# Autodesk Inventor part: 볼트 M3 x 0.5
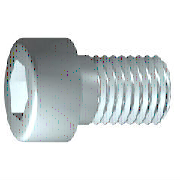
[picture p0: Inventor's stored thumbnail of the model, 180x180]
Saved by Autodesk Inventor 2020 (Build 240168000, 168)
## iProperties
Company: 한국ATC센터
IsCustomPart: 1
Created: 2015-12
Part Number: 볼트 M3 x 0.5
Material: 스테인리스강
Description: 6각머리 태핑 나사
Document SubType Name: Modeling
Standard: KS B 1003
Designer: mdu
Standards Organization: KS
Language: ko-KR
Size Designation: M 4 x 12
Categories: <MemberInstance><Categories><Category DisplayName="조임쇠" InternalName="e4da775c-781d-43d5-af7c-5136215cf5a6" Mnemonic="FSTN"><Category DisplayName="볼트" InternalN
Density: 8.08 g/cm^3
Mass: 1.35567 g
Surface Area: 2.48975 cm^2
Volume: 0.167781 cm^3
Appearance: 반광택
Author: mdu
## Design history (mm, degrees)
sketch "스케치1"
  geometry: L1 (-0.867, 0)-(15, 0); L2 (15, 0)-(15, 1.5); L3 (15, 1.5)-(1.25, 1.5); L4 (1.25, 1.5)-(0.943, 1.5); L5 (0.943, 1.5)-(0, 1.5); L6 (0, 1.5)-(0, 2.75); L7 (0, 2.75)-(-3, 2.75); L8 (-3, 2.75)-(-3, 1.443); L9 (-3, 1.443)-(-1.7, 1.443); L10 (-1.7, 1.443)-(-0.867, 0); L11 (-6.6, 0)-(18.6, 0) reference; L12 (0, -0.55)-(0, 3.3) reference; L13 (1.25, 1.5)-(0, 1.5)
  constraints: 22 end point, 6 parallel, 2 collinear, 2 perpendicular, 1 horizontal, 1 point on line
  dimensions: "d1" = 13.75 distance from line of L3.end L2 (= GEL); "d2" = 0.30683 distance of L4.end L3.end (computed from GAL); "d3" = 3 distance between parallel lines of L8 L6 (= KOH); "d4" = 1.3 distance of L8.end L9.end (= INTI); "d5" = 60 deg angle of L10 L1; "d6" = 3 diameter of L3 L1 (= GD); "d7" = 3 diameter of L5 L1 (= BDM); "d8" = 2.88675 diameter of L9 L1 (= 1.1547 x SW); "d9" = 5.5 diameter of L7 L1 (= KOD); "d26" = 15 distance between parallel lines of L12 L2 (= NLG)
revolve "본체" sketch "스케치1" stored, may be unused: angle "d10" = 90 deg
sketch "스케치2"
  geometry: L1 (0, -3.85)-(0, 3.85) reference; L2 (-3.85, 0)-(3.85, 0) reference; L3 (1.443, 0)-(0.722, -1.25); L4 (0.722, -1.25)-(-0.722, -1.25); L5 (-0.722, -1.25)-(-1.443, 0); L6 (-1.443, 0)-(-0.722, 1.25); L7 (-0.722, 1.25)-(0.722, 1.25); L8 (0.722, 1.25)-(1.443, 0); 2 further points
  constraints: 12 end point, 1 coincident, 1 horizontal alignment, 1 point on line, 12 other
extrude "슬롯" join sketch "스케치2" stored distance "d11" = 10; taper "d12" = 0 deg
workplane "Work Plane1"
fillet "Fillet2" dims "d30" = 0.1 (= R)
body "Solid1"
fillet "모깎기1" dims "d17" = 0.3 (= RR)
feature "스레드" dims "d13" = 13.75 (= GEL), "d14" = 0
chamfer "모따기1" distance "d15" = 0.30673 (= -0.5 x SPD + 0.5 x GD); stored, may be unused: second distance "d16" = 0.30673 (= GUL), angle "d27" = 45 deg
other parameters: "GD" = 3 (= NND) [user parameter; used in 2 equation terms], "NLG" = 15 [user parameter; used in 1 equation term], "GEL" = 13.75 [user parameter; used in 2 equation terms], "KOD" = 5.5 [user parameter; used in 1 equation term], "KOH" = 3 [user parameter; used in 1 equation term], "INTI" = 1.3 [user parameter; used in 1 equation term], "GAL" = 0.30673 (= 0.61345 x PTC) [user parameter; used in 1 equation term], "GUL" = 0.30673 (= 0.61345 x PTC) [user parameter; used in 1 equation term], "BDM" = 3 (= NND) [user parameter; used in 1 equation term], "SW" = 2.5 [user parameter; used in 2 equation terms], "RR" = 0.3 [user parameter; used in 1 equation term], "SPD" = 2.38655 (= NND - 1.2269 x PTC) [user parameter; used in 1 equation term], "d19" = 0, "d28" = 0, "d29" = 0, "R" = 0.1 [user parameter; used in 1 equation term], "PHH" = 0.1 [user parameter], "GD1" = 2.38655 (= THREADDIA - 1.2269 x PTC) [user parameter], "THREADDIA" = 3 [user parameter; used in 1 equation term], "FAWI" = 45 deg [user parameter], "PTC" = 0.5 [user parameter; used in 5 equation terms], "NND" = 3 [user parameter; used in 3 equation terms], "TOA" = 30 deg [user parameter], "E0" = 2.8875 (= 1.155 x SW) [user parameter]
